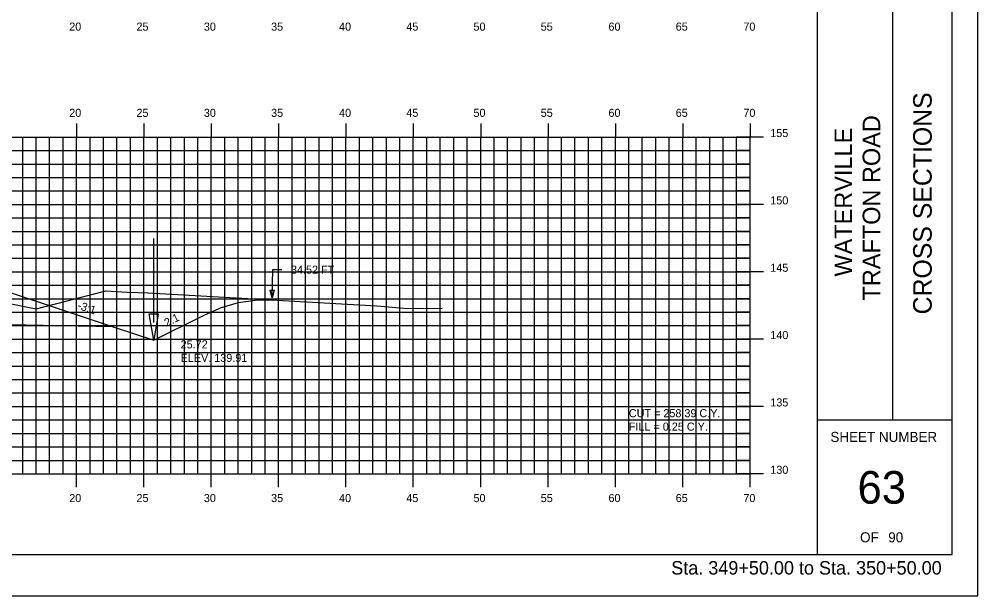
# Model space of a CAD drawing. Extents: x 1144529 to 1144699, y 608981 to 609091.
# Drawn here: x 1144627.6 to 1144698.8, y 608981.3 to 609024.1 of the extents above; entities that cross this region are included whole.
import ezdxf

# ---------------------------------------------------------------- set-up
doc = ezdxf.new("R2010")
doc.units = 0
for name, color, linetype in [('ANNOTATION', 7, 'Continuous'), ('BORDER', 7, 'Continuous'), ('D_Drainage_Ditch_Line', 7, 'Continuous'), ('D_Roadway_SlopeLines', 7, 'Continuous'), ('D_Roadway_SubGrade', 7, 'Continuous'), ('D_Text_Standard', 7, 'Continuous'), ('H_V ANNOTATION', 7, 'Continuous'), ('HIGHWAY_TITLE', 7, 'Continuous'), ('MAJOR', 7, 'Continuous'), ('MINOR', 7, 'Continuous'), ('PLOT BOUNDARY', 7, 'Continuous'), ('S_Roadway_Centerline', 7, 'Continuous')]:
    doc.layers.add(name, color=color, linetype=linetype)

msp = doc.modelspace()

# ---------------------------------------------------------------- linework, layer by layer
msp.add_lwpolyline([(1144571.423, 609006.407), (1144572.673, 609006.305), (1144573.923, 609006.053), (1144575.173, 609005.652), (1144576.423, 609005.102), (1144586.138, 609000.245), (1144589.138, 609001.245), (1144596.861, 609003.819), (1144596.862, 609003.819), (1144600.862, 609003.979), (1144611.862, 609004.199), (1144622.862, 609003.979), (1144626.862, 609003.819), (1144634.586, 609001.245), (1144637.586, 609000.245), (1144641.379, 609002.141), (1144642.629, 609002.679), (1144643.879, 609003.044), (1144645.129, 609003.234), (1144646.379, 609003.251)])
at = {"layer": 'BORDER'}
for p, q in [((1144686.863, 608984.335), (1144686.863, 609089.335)), ((1144692.454, 608994.338), (1144692.454, 609029.338)), ((1144686.863, 608994.338), (1144696.863, 608994.338))]:
    msp.add_line(p, q, dxfattribs=at)
msp.add_lwpolyline([(1144536.863, 608984.335), (1144696.863, 608984.335), (1144696.863, 609089.335), (1144536.863, 609089.335)], close=True, dxfattribs=at)
at = {"layer": 'D_Drainage_Ditch_Line'}
msp.add_line((1144637.586, 609001.557), (1144637.586, 609007.801), dxfattribs=at)
msp.add_lwpolyline([(1144637.258, 609002.213), (1144637.914, 609002.213), (1144637.586, 609000.245)], close=True, dxfattribs=at)
at = {"layer": 'D_Roadway_SlopeLines'}
for points in [[(1144637.586, 609000.245), (1144641.379, 609002.141), (1144642.629, 609002.679), (1144643.879, 609003.044), (1144645.129, 609003.234), (1144646.379, 609003.251)], [(1144634.586, 609001.245), (1144637.586, 609000.245)]]:
    msp.add_lwpolyline(points, dxfattribs=at)
at = {"layer": 'D_Roadway_SubGrade'}
msp.add_lwpolyline([(1144622.862, 609003.563), (1144622.862, 609003.729), (1144626.862, 609003.569), (1144626.862, 609003.819), (1144626.862, 609003.819), (1144634.586, 609001.245), (1144622.862, 609001.479)], close=True, dxfattribs=at)
at = {"layer": 'D_Text_Standard'}
msp.add_lwpolyline([(1144646.379, 609003.391), (1144646.421, 609005.492), (1144647.101, 609005.492)], dxfattribs=at)
msp.add_lwpolyline([(1144646.379, 609003.391), (1144646.245, 609003.976), (1144646.536, 609003.97)], close=True, dxfattribs=at)
at = {"layer": 'MAJOR'}
for p, q in [((1144631.862, 609016.337), (1144631.862, 609015.335)), ((1144636.862, 609016.337), (1144636.862, 609015.335)), ((1144641.862, 609016.337), (1144641.862, 609015.335)), ((1144646.862, 609016.337), (1144646.862, 609015.335)), ((1144651.862, 609016.337), (1144651.862, 609015.335)), ((1144656.862, 609016.337), (1144656.862, 609015.335)), ((1144661.862, 609016.337), (1144661.862, 609015.335)), ((1144666.862, 609016.337), (1144666.862, 609015.335)), ((1144671.862, 609016.337), (1144671.862, 609015.335)), ((1144676.862, 609016.337), (1144676.862, 609015.335)), ((1144681.862, 609016.337), (1144681.862, 609015.335)), ((1144541.862, 609015.335), (1144681.862, 609015.335)), ((1144541.862, 609015.335), (1144681.862, 609015.335)), ((1144631.862, 608990.335), (1144631.862, 609015.335)), ((1144636.862, 608990.335), (1144636.862, 609015.335)), ((1144641.862, 608990.335), (1144641.862, 609015.335)), ((1144646.862, 608990.335), (1144646.862, 609015.335)), ((1144651.862, 608990.335), (1144651.862, 609015.335)), ((1144656.862, 608990.335), (1144656.862, 609015.335)), ((1144661.862, 608990.335), (1144661.862, 609015.335)), ((1144666.862, 608990.335), (1144666.862, 609015.335)), ((1144671.862, 608990.335), (1144671.862, 609015.335)), ((1144676.862, 608990.335), (1144676.862, 609015.335)), ((1144682.864, 609015.335), (1144680.86, 609015.335)), ((1144681.862, 608990.335), (1144681.862, 609015.335)), ((1144681.862, 608990.335), (1144681.862, 609015.335)), ((1144541.862, 609010.335), (1144681.862, 609010.335)), ((1144682.864, 609010.335), (1144680.86, 609010.335)), ((1144541.862, 609005.335), (1144681.862, 609005.335)), ((1144682.864, 609005.335), (1144680.86, 609005.335)), ((1144541.862, 609000.335), (1144681.862, 609000.335)), ((1144682.864, 609000.335), (1144680.86, 609000.335)), ((1144541.862, 608995.335), (1144681.862, 608995.335)), ((1144682.864, 608995.335), (1144680.86, 608995.335)), ((1144541.862, 608990.335), (1144681.862, 608990.335)), ((1144541.862, 608990.335), (1144681.862, 608990.335)), ((1144631.862, 608989.333), (1144631.862, 608990.335)), ((1144636.862, 608989.333), (1144636.862, 608990.335)), ((1144641.862, 608989.333), (1144641.862, 608990.335)), ((1144646.862, 608989.333), (1144646.862, 608990.335)), ((1144651.862, 608989.333), (1144651.862, 608990.335)), ((1144656.862, 608989.333), (1144656.862, 608990.335)), ((1144661.862, 608989.333), (1144661.862, 608990.335)), ((1144666.862, 608989.333), (1144666.862, 608990.335)), ((1144671.862, 608989.333), (1144671.862, 608990.335)), ((1144676.862, 608989.333), (1144676.862, 608990.335)), ((1144682.864, 608990.335), (1144680.86, 608990.335)), ((1144681.862, 608989.333), (1144681.862, 608990.335))]:
    msp.add_line(p, q, dxfattribs=at)
at = {"layer": 'MINOR'}
for p, q in [((1144627.862, 608990.335), (1144627.862, 609015.335)), ((1144628.862, 608990.335), (1144628.862, 609015.335)), ((1144629.862, 608990.335), (1144629.862, 609015.335)), ((1144630.862, 608990.335), (1144630.862, 609015.335)), ((1144632.862, 608990.335), (1144632.862, 609015.335)), ((1144633.862, 608990.335), (1144633.862, 609015.335)), ((1144634.862, 608990.335), (1144634.862, 609015.335)), ((1144635.862, 608990.335), (1144635.862, 609015.335)), ((1144637.862, 608990.335), (1144637.862, 609015.335)), ((1144638.862, 608990.335), (1144638.862, 609015.335)), ((1144639.862, 608990.335), (1144639.862, 609015.335)), ((1144640.862, 608990.335), (1144640.862, 609015.335)), ((1144642.862, 608990.335), (1144642.862, 609015.335)), ((1144643.862, 608990.335), (1144643.862, 609015.335)), ((1144644.862, 608990.335), (1144644.862, 609015.335)), ((1144645.862, 608990.335), (1144645.862, 609015.335)), ((1144647.862, 608990.335), (1144647.862, 609015.335)), ((1144648.862, 608990.335), (1144648.862, 609015.335)), ((1144649.862, 608990.335), (1144649.862, 609015.335)), ((1144650.862, 608990.335), (1144650.862, 609015.335)), ((1144652.862, 608990.335), (1144652.862, 609015.335)), ((1144653.862, 608990.335), (1144653.862, 609015.335)), ((1144654.862, 608990.335), (1144654.862, 609015.335)), ((1144655.862, 608990.335), (1144655.862, 609015.335)), ((1144657.862, 608990.335), (1144657.862, 609015.335)), ((1144658.862, 608990.335), (1144658.862, 609015.335)), ((1144659.862, 608990.335), (1144659.862, 609015.335)), ((1144660.862, 608990.335), (1144660.862, 609015.335)), ((1144662.862, 608990.335), (1144662.862, 609015.335)), ((1144663.862, 608990.335), (1144663.862, 609015.335)), ((1144664.862, 608990.335), (1144664.862, 609015.335)), ((1144665.862, 608990.335), (1144665.862, 609015.335)), ((1144667.862, 608990.335), (1144667.862, 609015.335)), ((1144668.862, 608990.335), (1144668.862, 609015.335)), ((1144669.862, 608990.335), (1144669.862, 609015.335)), ((1144670.862, 608990.335), (1144670.862, 609015.335)), ((1144672.862, 608990.335), (1144672.862, 609015.335)), ((1144673.862, 608990.335), (1144673.862, 609015.335)), ((1144674.862, 608990.335), (1144674.862, 609015.335)), ((1144675.862, 608990.335), (1144675.862, 609015.335)), ((1144677.862, 608990.335), (1144677.862, 609015.335)), ((1144678.862, 608990.335), (1144678.862, 609015.335)), ((1144679.862, 608990.335), (1144679.862, 609015.335)), ((1144680.862, 608990.335), (1144680.862, 609015.335)), ((1144541.862, 609014.335), (1144681.862, 609014.335)), ((1144681.862, 609014.335), (1144680.86, 609014.335)), ((1144541.862, 609013.335), (1144681.862, 609013.335)), ((1144681.862, 609013.335), (1144680.86, 609013.335)), ((1144541.862, 609012.335), (1144681.862, 609012.335)), ((1144681.862, 609012.335), (1144680.86, 609012.335)), ((1144541.862, 609011.335), (1144681.862, 609011.335)), ((1144681.862, 609011.335), (1144680.86, 609011.335)), ((1144541.862, 609009.335), (1144681.862, 609009.335)), ((1144681.862, 609009.335), (1144680.86, 609009.335)), ((1144541.862, 609008.335), (1144681.862, 609008.335)), ((1144681.862, 609008.335), (1144680.86, 609008.335)), ((1144541.862, 609007.335), (1144681.862, 609007.335)), ((1144681.862, 609007.335), (1144680.86, 609007.335)), ((1144541.862, 609006.335), (1144681.862, 609006.335)), ((1144681.862, 609006.335), (1144680.86, 609006.335)), ((1144541.862, 609004.335), (1144681.862, 609004.335)), ((1144681.862, 609004.335), (1144680.86, 609004.335)), ((1144541.862, 609003.335), (1144681.862, 609003.335)), ((1144681.862, 609003.335), (1144680.86, 609003.335)), ((1144541.862, 609002.335), (1144681.862, 609002.335)), ((1144681.862, 609002.335), (1144680.86, 609002.335)), ((1144541.862, 609001.335), (1144681.862, 609001.335)), ((1144681.862, 609001.335), (1144680.86, 609001.335)), ((1144541.862, 608999.335), (1144681.862, 608999.335)), ((1144681.862, 608999.335), (1144680.86, 608999.335)), ((1144541.862, 608998.335), (1144681.862, 608998.335)), ((1144681.862, 608998.335), (1144680.86, 608998.335)), ((1144541.862, 608997.335), (1144681.862, 608997.335)), ((1144681.862, 608997.335), (1144680.86, 608997.335)), ((1144541.862, 608996.335), (1144681.862, 608996.335)), ((1144681.862, 608996.335), (1144680.86, 608996.335)), ((1144541.862, 608994.335), (1144681.862, 608994.335)), ((1144681.862, 608994.335), (1144680.86, 608994.335)), ((1144541.862, 608993.335), (1144681.862, 608993.335)), ((1144681.862, 608993.335), (1144680.86, 608993.335)), ((1144541.862, 608992.335), (1144681.862, 608992.335)), ((1144681.862, 608992.335), (1144680.86, 608992.335)), ((1144541.862, 608991.335), (1144681.862, 608991.335)), ((1144681.862, 608991.335), (1144680.86, 608991.335))]:
    msp.add_line(p, q, dxfattribs=at)
at = {"layer": 'PLOT BOUNDARY'}
msp.add_lwpolyline([(1144528.769, 608981.276), (1144698.769, 608981.276), (1144698.769, 609091.276), (1144528.769, 609091.276)], close=True, dxfattribs=at)
at = {"layer": 'S_Roadway_Centerline'}
msp.add_lwpolyline([(1144559.187, 609006.676), (1144578.978, 609006.241), (1144581.605, 609006.146), (1144590.889, 609003.306), (1144592.175, 609002.739), (1144592.604, 609002.838), (1144596.133, 609003.761), (1144597.846, 609003.878), (1144598.337, 609003.906), (1144599.767, 609003.934), (1144609.205, 609003.954), (1144611.065, 609003.88), (1144619.958, 609003.648), (1144620.511, 609003.593), (1144625.858, 609003.18), (1144626.506, 609003.065), (1144628.858, 609002.594), (1144634.039, 609003.929), (1144635.609, 609003.813), (1144637.17, 609003.769), (1144654.147, 609002.813), (1144656.428, 609002.61), (1144659.014, 609002.64)], dxfattribs=at)

# ---------------------------------------------------------------- texts
at = {"layer": 'ANNOTATION'}
for s, rotation, p in [('-3:1', 341.56521, (1144631.874, 609002.603)), ('2:1', 26.56505, (1144638.555, 609001.247))]:
    msp.add_text(s, height=0.6, rotation=rotation, dxfattribs=at).set_placement(p)
at = {"layer": 'BORDER'}
msp.add_text('CROSS SECTIONS', height=1.37787, rotation=90, dxfattribs=at).set_placement((1144695.347, 609002.172))
for s, height, p in [('SHEET NUMBER', 0.74527, (1144687.828, 608992.701)), ('63', 2.4194, (1144689.838, 608988.118)), ('OF', 0.7453, (1144690.029, 608985.248)), ('90', 0.7453, (1144692.119, 608985.248))]:
    msp.add_text(s, height=height, dxfattribs=at).set_placement(p)
at = {"layer": 'D_Text_Standard'}
for s, p in [('34.52 FT', (1144647.781, 609005.192)), ('25.72', (1144639.586, 608999.645)), ('ELEV. 139.91', (1144639.586, 608998.643)), ('CUT = 258.39 C.Y.', (1144672.862, 608994.535)), ('FILL = 0.25 C.Y.', (1144672.862, 608993.539))]:
    msp.add_text(s, height=0.6, dxfattribs=at).set_placement(p)
at = {"layer": 'H_V ANNOTATION'}
for s, height, p in [('20', 0.6, (1144631.316, 609023.235)), ('25', 0.6, (1144636.308, 609023.235)), ('30', 0.6, (1144641.311, 609023.235)), ('35', 0.6, (1144646.303, 609023.235)), ('40', 0.6, (1144651.348, 609023.235)), ('45', 0.6, (1144656.34, 609023.235)), ('50', 0.6, (1144661.327, 609023.235)), ('55', 0.6, (1144666.319, 609023.235)), ('60', 0.6, (1144671.348, 609023.235)), ('65', 0.6, (1144676.34, 609023.235)), ('70', 0.6, (1144681.364, 609023.235)), ('20', 0.6, (1144631.316, 609016.835)), ('25', 0.6, (1144636.308, 609016.835)), ('30', 0.6, (1144641.311, 609016.835)), ('35', 0.6, (1144646.303, 609016.835)), ('40', 0.6, (1144651.348, 609016.835)), ('45', 0.6, (1144656.34, 609016.835)), ('50', 0.6, (1144661.327, 609016.835)), ('55', 0.6, (1144666.319, 609016.835)), ('60', 0.6, (1144671.348, 609016.835)), ('65', 0.6, (1144676.34, 609016.835)), ('70', 0.6, (1144681.364, 609016.835)), ('155', 0.6, (1144683.362, 609015.335)), ('150', 0.6, (1144683.362, 609010.335)), ('145', 0.6, (1144683.362, 609005.335)), ('140', 0.6, (1144683.362, 609000.335)), ('135', 0.6, (1144683.362, 608995.335)), ('130', 0.6, (1144683.362, 608990.335)), ('20', 0.6, (1144631.316, 608988.235)), ('25', 0.6, (1144636.308, 608988.235)), ('30', 0.6, (1144641.311, 608988.235)), ('35', 0.6, (1144646.303, 608988.235)), ('40', 0.6, (1144651.348, 608988.235)), ('45', 0.6, (1144656.34, 608988.235)), ('50', 0.6, (1144661.327, 608988.235)), ('55', 0.6, (1144666.319, 608988.235)), ('60', 0.6, (1144671.348, 608988.235)), ('65', 0.6, (1144676.34, 608988.235)), ('70', 0.6, (1144681.364, 608988.235)), ('Sta. 349+50.00 to Sta. 350+50.00', 1.0002, (1144676.008, 608982.855))]:
    msp.add_text(s, height=height, dxfattribs=at).set_placement(p)
at = {"layer": 'HIGHWAY_TITLE'}
for s, height, p in [('TRAFTON ROAD', 1.30428, (1144691.522, 609003.201)), ('WATERVILLE', 1.3043, (1144689.435, 609004.98))]:
    msp.add_text(s, height=height, rotation=90, dxfattribs=at).set_placement(p)

doc.saveas('drawing.dxf')
